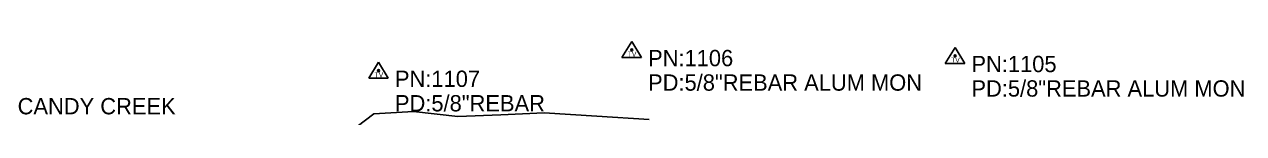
# Model space of a CAD drawing. Extents: x 1676038 to 1677961, y 226475 to 233854.
# Drawn here: x 1677588 to 1677960.7, y 229139.3 to 229162.4 of the extents above; entities that cross this region are included whole.
import ezdxf

# ---------------------------------------------------------------- set-up
doc = ezdxf.new("R2010")
doc.units = 0
for name, color, linetype in [('S_SECONDARY_CTL', 7, 'Continuous'), ('S_SECONDARY_CTL_ANNOT', 7, 'Continuous'), ('S_STREAM', 7, 'Continuous'), ('S_SURVEY_TEXT_ANNOT', 7, 'Continuous')]:
    doc.layers.add(name, color=color, linetype=linetype)

msp = doc.modelspace()

# ---------------------------------------------------------------- linework, layer by layer
at = {"layer": 'S_SECONDARY_CTL'}
for p, q in [((1677773.65, 229162.39), (1677770.64, 229157.43)), ((1677773.65, 229162.39), (1677776.6, 229157.43)), ((1677770.64, 229157.43), (1677776.6, 229157.43)), ((1677872.49, 229160.57), (1677869.48, 229155.61)), ((1677872.49, 229160.57), (1677875.44, 229155.61)), ((1677696.27, 229156.04), (1677693.26, 229151.09)), ((1677696.27, 229156.04), (1677699.22, 229151.09)), ((1677869.48, 229155.61), (1677875.44, 229155.61)), ((1677693.26, 229151.09), (1677699.22, 229151.09))]:
    msp.add_line(p, q, dxfattribs=at)
for centre, radius in [((1677773.65, 229159.78), 0.311), ((1677773.65, 229159.78), 0.183), ((1677773.65, 229159.78), 0.103), ((1677872.49, 229157.96), 0.311), ((1677872.49, 229157.96), 0.183), ((1677872.49, 229157.96), 0.103), ((1677696.27, 229153.43), 0.311), ((1677696.27, 229153.43), 0.183), ((1677696.27, 229153.43), 0.103)]:
    msp.add_circle(centre, radius, dxfattribs=at)
at = {"layer": 'S_STREAM'}
msp.add_lwpolyline([(1677779.03, 229138.44), (1677762.96, 229139.45), (1677746.89, 229140.47), (1677733.68, 229139.9), (1677720.47, 229139.34), (1677706.92, 229140.91), (1677694.84, 229140.14), (1677689.74, 229136.3)], dxfattribs=at)

# ---------------------------------------------------------------- texts
at = {"layer": 'S_SECONDARY_CTL'}
for p in [(1677772.44, 229157.76), (1677871.28, 229155.95), (1677695.06, 229151.42)]:
    msp.add_text('TV', height=1.5, rotation=360, dxfattribs=at).set_placement(p)
at = {"layer": 'S_SECONDARY_CTL_ANNOT'}
for s, p in [('PN:1106', (1677778.65, 229154.78)), ('PN:1105', (1677877.49, 229152.96)), ('PN:1107', (1677701.27, 229148.43)), ('PD:5/8"REBAR ALUM MON', (1677778.65, 229147.28)), ('PD:5/8"REBAR ALUM MON', (1677877.49, 229145.46)), ('PD:5/8"REBAR', (1677701.27, 229140.93))]:
    msp.add_text(s, height=5, dxfattribs=at).set_placement(p)
at = {"layer": 'S_SURVEY_TEXT_ANNOT'}
msp.add_text('CANDY CREEK CANDY CREEK', height=5, dxfattribs=at).set_placement((1677535.79, 229140.03))

doc.saveas('drawing.dxf')
